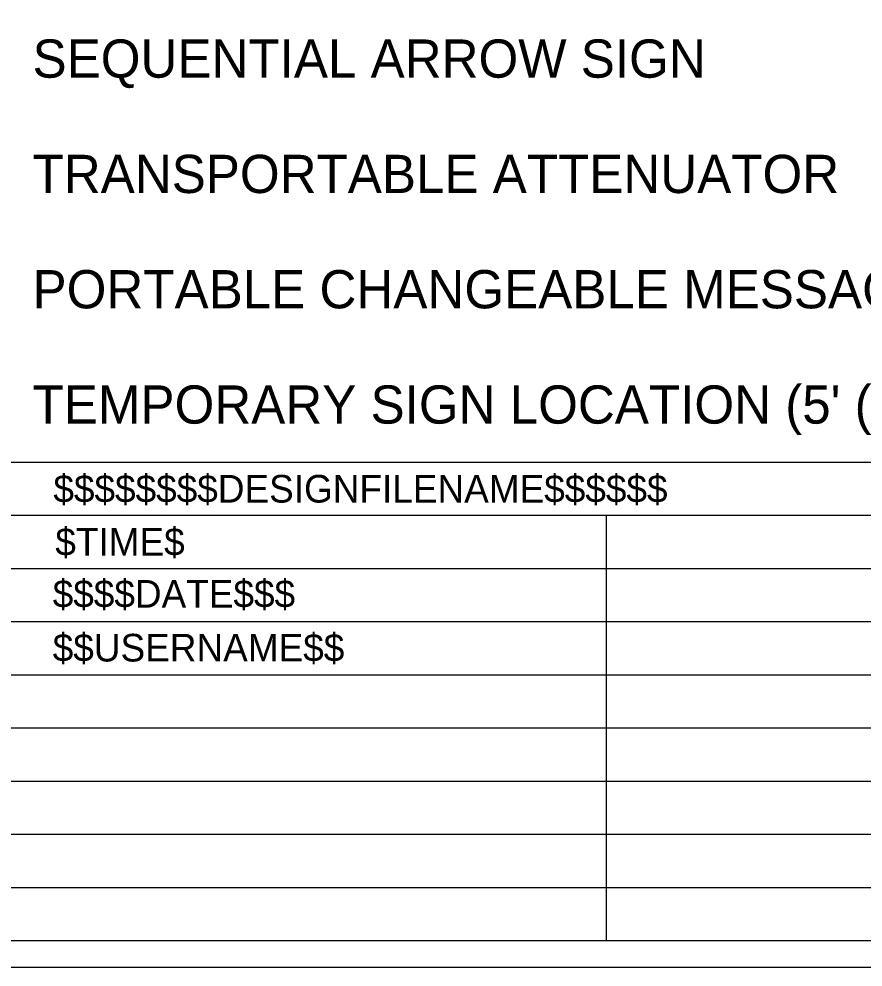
# Model space of a CAD drawing. Extents: x 99988 to 100172, y 99995 to 100047.
# Drawn here: x 100000.796 to 100002.784, y 99999.937 to 100002.169 of the extents above; entities that cross this region are included whole.
import ezdxf

# ---------------------------------------------------------------- set-up
doc = ezdxf.new("R2010")
doc.units = 0
for name, color, linetype in [('SH_DE_DetailBody1Text', 7, 'Continuous'), ('SH_GI_PlotLimits', 7, 'Continuous'), ('SH_GI_SheetBorder', 7, 'Continuous'), ('SH_GI_TitleBlockText', 7, 'Continuous')]:
    doc.layers.add(name, color=color, linetype=linetype)

msp = doc.modelspace()

# ---------------------------------------------------------------- linework, layer by layer
at = {"layer": 'SH_GI_PlotLimits'}
msp.add_lwpolyline([(99999.3125, 99999.9375), (100015.8125, 99999.9375), (100015.8125, 100010.4375), (99999.3125, 100010.4375)], close=True, dxfattribs=at)
at = {"layer": 'SH_GI_SheetBorder'}
for p, q in [((100000, 100001.1259), (100015.75, 100001.1259)), ((100000, 100001.0008), (100007.4566, 100001.0008)), ((100002.179, 100001.0008), (100002.179, 100000)), ((100000, 100000.8757), (100002.1821, 100000.8757)), ((100002.1821, 100000.8757), (100005.4466, 100000.8757)), ((100000, 100000.7506), (100002.1821, 100000.7506)), ((100002.1821, 100000.7506), (100005.4466, 100000.7506)), ((100000, 100000.6255), (100005.4466, 100000.6255)), ((100000, 100000.5004), (100005.4466, 100000.5004)), ((100000, 100000.3753), (100005.4466, 100000.3753)), ((100000, 100000.2502), (100005.4466, 100000.2502)), ((100000, 100000.1251), (100005.4466, 100000.1251)), ((100000, 100000), (100015.75, 100000))]:
    msp.add_line(p, q, dxfattribs=at)

# ---------------------------------------------------------------- texts
at = {"layer": 'SH_DE_DetailBody1Text'}
for s, p in [('SEQUENTIAL ARROW SIGN', (100000.8284, 100002.0309)), ('TRANSPORTABLE ATTENUATOR', (100000.8284, 100001.7594)), ('PORTABLE CHANGEABLE MESSAGE SIGN', (100000.8284, 100001.488)), ("TEMPORARY SIGN LOCATION (5' (FT) MOUNTING HEIGHT)", (100000.8284, 100001.2166))]:
    msp.add_text(s, height=0.09, dxfattribs=at).set_placement(p)
at = {"layer": 'SH_GI_TitleBlockText'}
for s, height, p in [('$$$$$$$$DESIGNFILENAME$$$$$$', 0.065052, (100000.8775, 100001.0308)), ('$TIME$', 0.06505, (100000.882, 100000.9059)), ('$$$$DATE$$$', 0.065052, (100000.8759, 100000.7835)), ('$$USERNAME$$', 0.065052, (100000.8759, 100000.6567))]:
    msp.add_text(s, height=height, dxfattribs=at).set_placement(p)

doc.saveas('drawing.dxf')
